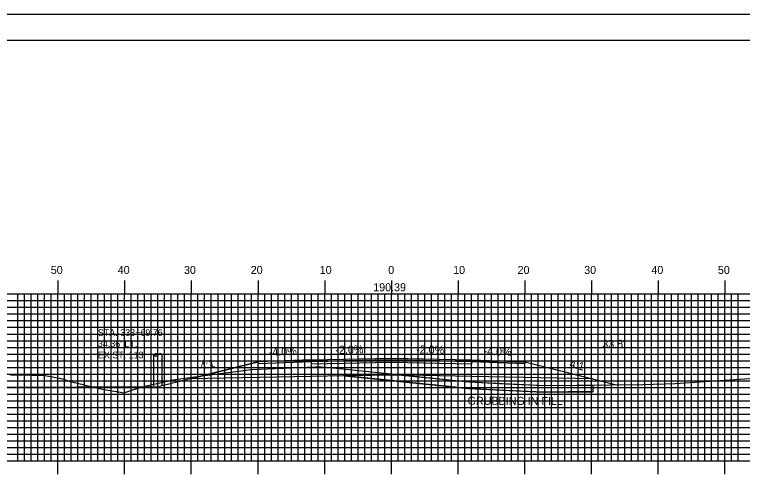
# Model space of a CAD drawing. Extents: x 1822785 to 1823129, y 442591 to 442811.
# Drawn here: x 1822894.8 to 1823003.9, y 442741.2 to 442810.5 of the extents above; entities that cross this region are included whole.
import ezdxf

# ---------------------------------------------------------------- set-up
doc = ezdxf.new("R2010")
doc.units = 0
for name, color, linetype in [('ANNOTATION', 7, 'Continuous'), ('BORDER', 7, 'Continuous'), ('D_Roadway_Centerline', 7, 'Continuous'), ('D_Roadway_Centerline_Text', 7, 'Continuous'), ('D_Roadway_Edge_Shoulder', 7, 'Continuous'), ('D_Roadway_Edge_TW', 7, 'Continuous'), ('D_Roadway_Pavement', 7, 'Continuous'), ('D_Roadway_SlopeLines', 7, 'Continuous'), ('D_Roadway_SubGrade', 7, 'Continuous'), ('D_Text_Monospaced', 7, 'Continuous'), ('D_Text_Standard', 7, 'Continuous'), ('GRUBBING IN FILL', 7, 'Continuous'), ('H_V ANNOTATION', 7, 'Continuous'), ('MAJOR', 7, 'Continuous'), ('MINOR', 7, 'Continuous'), ('PLOT BOUNDARY', 7, 'Continuous'), ('S_Roadway_Centerline', 7, 'Continuous'), ('S_Utilities_Pole_Power', 7, 'Continuous')]:
    doc.layers.add(name, color=color, linetype=linetype)

msp = doc.modelspace()

# ---------------------------------------------------------------- linework, layer by layer
at = {"layer": 'ANNOTATION'}
msp.add_line((1822839.41, 442754.41), (1822916.5, 442754.8), dxfattribs=at)
at = {"layer": 'BORDER'}
msp.add_lwpolyline([(1822801.68, 442596.67), (1823121.68, 442596.67), (1823121.68, 442806.67), (1822801.68, 442806.67)], close=True, dxfattribs=at)
at = {"layer": 'D_Roadway_Edge_Shoulder'}
for points in [[(1822939.28, 442758.81), (1822931.28, 442758.49), (1822931.28, 442758.24), (1822939.28, 442758.56)], [(1822963.28, 442758.81), (1822971.28, 442758.49), (1822971.28, 442758.24), (1822963.28, 442758.56)]]:
    msp.add_lwpolyline(points, close=True, dxfattribs=at)
at = {"layer": 'D_Roadway_Edge_TW'}
msp.add_lwpolyline([(1822939.28, 442758.56), (1822939.28, 442758.81), (1822951.28, 442759.05), (1822963.28, 442758.81), (1822963.28, 442758.56), (1822951.28, 442758.8)], close=True, dxfattribs=at)
at = {"layer": 'D_Roadway_Pavement'}
msp.add_lwpolyline([(1822939.28, 442758.15), (1822939.28, 442758.56), (1822951.28, 442758.8), (1822963.28, 442758.56), (1822963.28, 442758.15), (1822951.28, 442758.39)], close=True, dxfattribs=at)
at = {"layer": 'D_Roadway_SlopeLines'}
for points in [[(1822931.28, 442758.49), (1822916.5, 442754.8)], [(1822971.28, 442758.49), (1822985.03, 442755.06)]]:
    msp.add_lwpolyline(points, dxfattribs=at)
at = {"layer": 'D_Roadway_SubGrade'}
msp.add_lwpolyline([(1822939.28, 442756.31), (1822921.11, 442755.95), (1822931.28, 442758.49), (1822931.28, 442758.24), (1822939.28, 442758.56), (1822951.28, 442758.8), (1822963.28, 442758.56), (1822971.28, 442758.24), (1822971.28, 442758.49), (1822981.46, 442755.95), (1822963.28, 442756.31), (1822951.28, 442756.55)], close=True, dxfattribs=at)
at = {"layer": 'GRUBBING IN FILL'}
msp.add_line((1822981.46, 442755.02), (1822981.46, 442754.02), dxfattribs=at)
msp.add_line((1822981.46, 442755.02), (1822981.46, 442754.02), dxfattribs=at)
for points in [[(1822944.25, 442756.41), (1822945.28, 442756.43), (1822951.28, 442756.55), (1822951.28, 442755.68)], [(1822944.25, 442756.41), (1822945.28, 442756.43), (1822951.28, 442756.55), (1822951.28, 442755.68)], [(1822951.28, 442756.55), (1822952.84, 442756.52), (1822962.86, 442755.48), (1822968.49, 442755.21), (1822974.11, 442754.95), (1822981.46, 442755.02), (1822981.46, 442754.02), (1822977.78, 442753.98), (1822974.09, 442753.95), (1822968.44, 442754.21), (1822962.79, 442754.48), (1822953.52, 442755.45), (1822951.28, 442755.68)], [(1822951.28, 442756.55), (1822952.84, 442756.52), (1822962.86, 442755.48), (1822968.49, 442755.21), (1822974.11, 442754.95), (1822981.46, 442755.02), (1822981.46, 442754.02), (1822977.78, 442753.98), (1822974.09, 442753.95), (1822968.44, 442754.21), (1822962.79, 442754.48), (1822953.52, 442755.45), (1822951.28, 442755.68)]]:
    msp.add_lwpolyline(points, close=True, dxfattribs=at)
msp.add_lwpolyline([(1822944.25, 442756.41), (1822962.79, 442754.48), (1822974.09, 442753.95), (1822981.46, 442754.02)], dxfattribs=at)
msp.add_lwpolyline([(1822944.25, 442756.41), (1822962.79, 442754.48), (1822974.09, 442753.95), (1822981.46, 442754.02)], dxfattribs=at)
at = {"layer": 'MAJOR'}
for p, q in [((1822901.28, 442770.67), (1822901.28, 442768.67)), ((1822911.28, 442770.67), (1822911.28, 442768.67)), ((1822921.28, 442770.67), (1822921.28, 442768.67)), ((1822931.28, 442770.67), (1822931.28, 442768.67)), ((1822941.28, 442770.67), (1822941.28, 442768.67)), ((1822951.28, 442770.67), (1822951.28, 442768.67)), ((1822961.28, 442770.67), (1822961.28, 442768.67)), ((1822971.28, 442770.67), (1822971.28, 442768.67)), ((1822981.28, 442770.67), (1822981.28, 442768.67)), ((1822991.28, 442770.67), (1822991.28, 442768.67)), ((1823001.28, 442770.67), (1823001.28, 442768.67)), ((1822811.28, 442768.67), (1823091.28, 442768.67)), ((1822811.28, 442768.67), (1823091.28, 442768.67)), ((1822901.28, 442743.67), (1822901.28, 442768.67)), ((1822911.28, 442743.67), (1822911.28, 442768.67)), ((1822921.28, 442743.67), (1822921.28, 442768.67)), ((1822931.28, 442743.67), (1822931.28, 442768.67)), ((1822941.28, 442743.67), (1822941.28, 442768.67)), ((1822951.28, 442743.67), (1822951.28, 442768.67)), ((1822961.28, 442743.67), (1822961.28, 442768.67)), ((1822971.28, 442743.67), (1822971.28, 442768.67)), ((1822981.28, 442743.67), (1822981.28, 442768.67)), ((1822991.28, 442743.67), (1822991.28, 442768.67)), ((1823001.28, 442743.67), (1823001.28, 442768.67)), ((1822811.28, 442763.67), (1823091.28, 442763.67)), ((1822811.28, 442758.67), (1823091.28, 442758.67)), ((1822811.28, 442753.67), (1823091.28, 442753.67)), ((1822811.28, 442748.67), (1823091.28, 442748.67)), ((1822811.28, 442743.67), (1823091.28, 442743.67)), ((1822811.28, 442743.67), (1823091.28, 442743.67)), ((1822901.28, 442741.66), (1822901.28, 442743.67)), ((1822911.28, 442741.66), (1822911.28, 442743.67)), ((1822921.28, 442741.66), (1822921.28, 442743.67)), ((1822931.28, 442741.66), (1822931.28, 442743.67)), ((1822941.28, 442741.66), (1822941.28, 442743.67)), ((1822951.28, 442741.66), (1822951.28, 442743.67)), ((1822961.28, 442741.66), (1822961.28, 442743.67)), ((1822971.28, 442741.66), (1822971.28, 442743.67)), ((1822981.28, 442741.66), (1822981.28, 442743.67)), ((1822991.28, 442741.66), (1822991.28, 442743.67)), ((1823001.28, 442741.66), (1823001.28, 442743.67))]:
    msp.add_line(p, q, dxfattribs=at)
at = {"layer": 'MINOR'}
for p, q in [((1822811.28, 442767.67), (1823091.28, 442767.67)), ((1822895.28, 442743.67), (1822895.28, 442768.67)), ((1822896.28, 442743.67), (1822896.28, 442768.67)), ((1822897.28, 442743.67), (1822897.28, 442768.67)), ((1822898.28, 442743.67), (1822898.28, 442768.67)), ((1822899.28, 442743.67), (1822899.28, 442768.67)), ((1822900.28, 442743.67), (1822900.28, 442768.67)), ((1822902.28, 442743.67), (1822902.28, 442768.67)), ((1822903.28, 442743.67), (1822903.28, 442768.67)), ((1822904.28, 442743.67), (1822904.28, 442768.67)), ((1822905.28, 442743.67), (1822905.28, 442768.67)), ((1822906.28, 442743.67), (1822906.28, 442768.67)), ((1822907.28, 442743.67), (1822907.28, 442768.67)), ((1822908.28, 442743.67), (1822908.28, 442768.67)), ((1822909.28, 442743.67), (1822909.28, 442768.67)), ((1822910.28, 442743.67), (1822910.28, 442768.67)), ((1822912.28, 442743.67), (1822912.28, 442768.67)), ((1822913.28, 442743.67), (1822913.28, 442768.67)), ((1822914.28, 442743.67), (1822914.28, 442768.67)), ((1822915.28, 442743.67), (1822915.28, 442768.67)), ((1822916.28, 442743.67), (1822916.28, 442768.67)), ((1822917.28, 442743.67), (1822917.28, 442768.67)), ((1822918.28, 442743.67), (1822918.28, 442768.67)), ((1822919.28, 442743.67), (1822919.28, 442768.67)), ((1822920.28, 442743.67), (1822920.28, 442768.67)), ((1822922.28, 442743.67), (1822922.28, 442768.67)), ((1822923.28, 442743.67), (1822923.28, 442768.67)), ((1822924.28, 442743.67), (1822924.28, 442768.67)), ((1822925.28, 442743.67), (1822925.28, 442768.67)), ((1822926.28, 442743.67), (1822926.28, 442768.67)), ((1822927.28, 442743.67), (1822927.28, 442768.67)), ((1822928.28, 442743.67), (1822928.28, 442768.67)), ((1822929.28, 442743.67), (1822929.28, 442768.67)), ((1822930.28, 442743.67), (1822930.28, 442768.67)), ((1822932.28, 442743.67), (1822932.28, 442768.67)), ((1822933.28, 442743.67), (1822933.28, 442768.67)), ((1822934.28, 442743.67), (1822934.28, 442768.67)), ((1822935.28, 442743.67), (1822935.28, 442768.67)), ((1822936.28, 442743.67), (1822936.28, 442768.67)), ((1822937.28, 442743.67), (1822937.28, 442768.67)), ((1822938.28, 442743.67), (1822938.28, 442768.67)), ((1822939.28, 442743.67), (1822939.28, 442768.67)), ((1822940.28, 442743.67), (1822940.28, 442768.67)), ((1822942.28, 442743.67), (1822942.28, 442768.67)), ((1822943.28, 442743.67), (1822943.28, 442768.67)), ((1822944.28, 442743.67), (1822944.28, 442768.67)), ((1822945.28, 442743.67), (1822945.28, 442768.67)), ((1822946.28, 442743.67), (1822946.28, 442768.67)), ((1822947.28, 442743.67), (1822947.28, 442768.67)), ((1822948.28, 442743.67), (1822948.28, 442768.67)), ((1822949.28, 442743.67), (1822949.28, 442768.67)), ((1822950.28, 442743.67), (1822950.28, 442768.67)), ((1822952.28, 442743.67), (1822952.28, 442768.67)), ((1822953.28, 442743.67), (1822953.28, 442768.67)), ((1822954.28, 442743.67), (1822954.28, 442768.67)), ((1822955.28, 442743.67), (1822955.28, 442768.67)), ((1822956.28, 442743.67), (1822956.28, 442768.67)), ((1822957.28, 442743.67), (1822957.28, 442768.67)), ((1822958.28, 442743.67), (1822958.28, 442768.67)), ((1822959.28, 442743.67), (1822959.28, 442768.67)), ((1822960.28, 442743.67), (1822960.28, 442768.67)), ((1822962.28, 442743.67), (1822962.28, 442768.67)), ((1822963.28, 442743.67), (1822963.28, 442768.67)), ((1822964.28, 442743.67), (1822964.28, 442768.67)), ((1822965.28, 442743.67), (1822965.28, 442768.67)), ((1822966.28, 442743.67), (1822966.28, 442768.67)), ((1822967.28, 442743.67), (1822967.28, 442768.67)), ((1822968.28, 442743.67), (1822968.28, 442768.67)), ((1822969.28, 442743.67), (1822969.28, 442768.67)), ((1822970.28, 442743.67), (1822970.28, 442768.67)), ((1822972.28, 442743.67), (1822972.28, 442768.67)), ((1822973.28, 442743.67), (1822973.28, 442768.67)), ((1822974.28, 442743.67), (1822974.28, 442768.67)), ((1822975.28, 442743.67), (1822975.28, 442768.67)), ((1822976.28, 442743.67), (1822976.28, 442768.67)), ((1822977.28, 442743.67), (1822977.28, 442768.67)), ((1822978.28, 442743.67), (1822978.28, 442768.67)), ((1822979.28, 442743.67), (1822979.28, 442768.67)), ((1822980.28, 442743.67), (1822980.28, 442768.67)), ((1822982.28, 442743.67), (1822982.28, 442768.67)), ((1822983.28, 442743.67), (1822983.28, 442768.67)), ((1822984.28, 442743.67), (1822984.28, 442768.67)), ((1822985.28, 442743.67), (1822985.28, 442768.67)), ((1822986.28, 442743.67), (1822986.28, 442768.67)), ((1822987.28, 442743.67), (1822987.28, 442768.67)), ((1822988.28, 442743.67), (1822988.28, 442768.67)), ((1822989.28, 442743.67), (1822989.28, 442768.67)), ((1822990.28, 442743.67), (1822990.28, 442768.67)), ((1822992.28, 442743.67), (1822992.28, 442768.67)), ((1822993.28, 442743.67), (1822993.28, 442768.67)), ((1822994.28, 442743.67), (1822994.28, 442768.67)), ((1822995.28, 442743.67), (1822995.28, 442768.67)), ((1822996.28, 442743.67), (1822996.28, 442768.67)), ((1822997.28, 442743.67), (1822997.28, 442768.67)), ((1822998.28, 442743.67), (1822998.28, 442768.67)), ((1822999.28, 442743.67), (1822999.28, 442768.67)), ((1823000.28, 442743.67), (1823000.28, 442768.67)), ((1823002.28, 442743.67), (1823002.28, 442768.67)), ((1823003.28, 442743.67), (1823003.28, 442768.67)), ((1822811.28, 442766.67), (1823091.28, 442766.67)), ((1822811.28, 442765.67), (1823091.28, 442765.67)), ((1822811.28, 442764.67), (1823091.28, 442764.67)), ((1822811.28, 442762.67), (1823091.28, 442762.67)), ((1822811.28, 442761.67), (1823091.28, 442761.67)), ((1822811.28, 442760.67), (1823091.28, 442760.67)), ((1822811.28, 442759.67), (1823091.28, 442759.67)), ((1822811.28, 442757.67), (1823091.28, 442757.67)), ((1822811.28, 442756.67), (1823091.28, 442756.67)), ((1822811.28, 442755.67), (1823091.28, 442755.67)), ((1822811.28, 442754.67), (1823091.28, 442754.67)), ((1822811.28, 442752.67), (1823091.28, 442752.67)), ((1822811.28, 442751.67), (1823091.28, 442751.67)), ((1822811.28, 442750.67), (1823091.28, 442750.67)), ((1822811.28, 442749.67), (1823091.28, 442749.67)), ((1822811.28, 442747.67), (1823091.28, 442747.67)), ((1822811.28, 442746.67), (1823091.28, 442746.67)), ((1822811.28, 442745.67), (1823091.28, 442745.67)), ((1822811.28, 442744.67), (1823091.28, 442744.67))]:
    msp.add_line(p, q, dxfattribs=at)
at = {"layer": 'PLOT BOUNDARY'}
msp.add_lwpolyline([(1822785.5, 442590.55), (1823125.5, 442590.55), (1823125.5, 442810.55), (1822785.5, 442810.55)], close=True, dxfattribs=at)
at = {"layer": 'S_Roadway_Centerline'}
msp.add_lwpolyline([(1822894.15, 442756.56), (1822897.24, 442756.49), (1822899.09, 442756.49), (1822900.45, 442756.24), (1822901.99, 442755.96), (1822902.99, 442755.61), (1822904.81, 442755.15), (1822905.98, 442754.86), (1822908.16, 442754.35), (1822910.37, 442754.01), (1822911.17, 442753.86), (1822912.96, 442754.45), (1822914.8, 442754.97), (1822918.56, 442755.81), (1822922.15, 442756.28), (1822930.25, 442757.36), (1822939.84, 442757.74), (1822940.75, 442757.75), (1822941.53, 442757.7), (1822962.86, 442755.48), (1822974.11, 442754.95), (1822988.96, 442755.1), (1822993.8, 442755.24), (1823007.16, 442756.13)], dxfattribs=at)
at = {"layer": 'S_Utilities_Pole_Power'}
for p, q in [((1822915.68, 442759.53), (1822915.83, 442759.64)), ((1822915.68, 442754.91), (1822915.68, 442759.53)), ((1822915.83, 442759.42), (1822915.68, 442759.53)), ((1822916.14, 442759.64), (1822916.3, 442759.53)), ((1822916.3, 442759.53), (1822916.14, 442759.42)), ((1822916.46, 442759.64), (1822916.3, 442759.53)), ((1822916.93, 442759.53), (1822916.77, 442759.64)), ((1822916.93, 442754.91), (1822916.93, 442759.53))]:
    msp.add_line(p, q, dxfattribs=at)
for centre, start, end in [((1822915.99, 442759.42), 90, 125.2644), ((1822915.99, 442759.64), 234.7356, 270), ((1822915.99, 442759.42), 54.7356, 90), ((1822915.99, 442759.64), 270, 305.2644), ((1822916.61, 442759.42), 90, 125.2644), ((1822916.61, 442759.42), 54.7356, 90)]:
    msp.add_arc(centre, 0.271, start, end, dxfattribs=at)

# ---------------------------------------------------------------- texts
at = {"layer": 'ANNOTATION'}
for s, rotation, p in [('-4.0%', 2.2906, (1822932.91, 442759.36)), ('-2.0%', 1.1458, (1822942.89, 442759.69)), ('-2.0%', 358.8542, (1822954.97, 442759.78)), ('-4.0%', 357.7094, (1822965.07, 442759.54)), ('4:1', 14.0362, (1822922.73, 442757.22)), ('4:1', 345.9638, (1822977.88, 442757.71))]:
    msp.add_text(s, height=1.2, rotation=rotation, dxfattribs=at).set_placement(p)
at = {"layer": 'D_Roadway_Centerline'}
for s in ['C', 'L']:
    msp.add_text(s, height=0.0146, dxfattribs=at).set_placement((1822951.28, 442759.05))
at = {"layer": 'D_Roadway_Centerline_Text'}
msp.add_text('190.39', height=1.2, dxfattribs=at).set_placement((1822948.55, 442769.08))
at = {"layer": 'D_Text_Monospaced'}
for s, p in [('STA. 333+69.76', (1822907.28, 442762.38)), ("34.36' LT.", (1822907.28, 442760.71)), ('EXIST. 113', (1822907.28, 442759.03))]:
    msp.add_text(s, height=1, dxfattribs=at).set_placement(p)
at = {"layer": 'D_Text_Standard'}
msp.add_text("33.8'", height=1.2, dxfattribs=at).set_placement((1822982.89, 442760.59))
at = {"layer": 'GRUBBING IN FILL'}
msp.add_text('GRUBBING IN FILL', height=1.2, rotation=359.8053, dxfattribs=at).set_placement((1822962.7, 442752.07))
at = {"layer": 'H_V ANNOTATION'}
for s, p in [('50', (1822900.21, 442771.67)), ('40', (1822910.25, 442771.67)), ('30', (1822920.18, 442771.67)), ('20', (1822930.19, 442771.67)), ('10', (1822940.53, 442771.67)), ('0', (1822950.8, 442771.67)), ('10', (1822960.53, 442771.67)), ('20', (1822970.19, 442771.67)), ('30', (1822980.18, 442771.67)), ('40', (1822990.25, 442771.67)), ('50', (1823000.21, 442771.67))]:
    msp.add_text(s, height=1.2, dxfattribs=at).set_placement(p)

doc.saveas('drawing.dxf')
